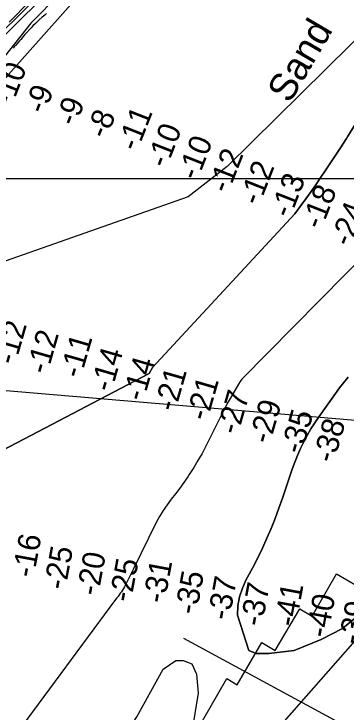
# Model space of a CAD drawing. Extents: x 3271442 to 3309282, y 752266 to 777610.
# Drawn here: x 3288016 to 3289012, y 762104 to 764198 of the extents above; entities that cross this region are included whole.
import ezdxf

# ---------------------------------------------------------------- set-up
doc = ezdxf.new("R2010")
doc.units = 0
for name, color, linetype in [('V-GRID-MAJR', 7, 'Continuous'), ('V-RIVR-EDGE', 7, 'Continuous'), ('V-RIVR-IDEN', 7, 'Continuous'), ('V-RIVR-RANG', 7, 'Continuous'), ('V-RRAP-RVMT', 7, 'Continuous'), ('V-SITE-VEGE', 7, 'Continuous'), ('V-TOPO-DPTH', 7, 'Continuous'), ('V-TOPO-MINR', 7, 'Continuous'), ('V-TOPO-WATR', 7, 'Continuous'), ('V-UTIL-LINE', 7, 'Continuous')]:
    doc.layers.add(name, color=color, linetype=linetype)

msp = doc.modelspace()

# ---------------------------------------------------------------- linework, layer by layer
at = {"layer": 'V-GRID-MAJR'}
msp.add_spline([(3275589.54, 763703.55), (3280833.333, 763703.169), (3286077.126, 763703.55), (3291320.919, 763704.694), (3296564.7120000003, 763706.601), (3301808.505, 763709.27), (3307052.2970000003, 763712.703), (3307052.298, 763712.703)], degree=3, dxfattribs=at)
at = {"layer": 'V-RIVR-EDGE'}
msp.add_lwpolyline([(3288063.4095426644, 764236.6794993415), (3288001.5274757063, 764172.9346756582)], dxfattribs=at)
at = {"layer": 'V-RIVR-RANG'}
msp.add_line((3289422.6719, 761839.2634), (3288525.1781, 762323.9333000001), dxfattribs=at)
at = {"layer": 'V-RRAP-RVMT'}
msp.add_lwpolyline([(3288581.339000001, 762077.719999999), (3288654.822000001, 762203.986999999), (3288685.260000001, 762185.760999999), (3288759.040000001, 762311.9149999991), (3288799.675000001, 762288.7039999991), (3288873.009000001, 762413.260999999), (3288910.816000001, 762391.6819999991), (3288983.352000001, 762518.167999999), (3289076.977000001, 762464.6769999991), (3289150.638000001, 762590.8879999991), (3289182.3570000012, 762571.8289999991), (3289254.390000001, 762698.454999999), (3289295.293000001, 762675.1009999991), (3289368.5190000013, 762802.7179999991), (3289377.962000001, 762796.954999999), (3289450.256000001, 762923.790999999), (3289468.066000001, 762913.130999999), (3289533.118000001, 763025.863999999), (3289582.620731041, 762997.3884135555)], dxfattribs=at)
at = {"layer": 'V-SITE-VEGE'}
msp.add_lwpolyline([(3288113.505, 764199.255), (3288110.923, 764197.062), (3288107.9760000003, 764194.87), (3288100.23, 764188.659), (3288091.375, 764180.2440000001), (3288085.1, 764174.028), (3288079.932, 764168.906), (3288072.551, 764161.957), (3288067.384, 764156.835), (3288065.168, 764154.275), (3288051.879, 764140.002), (3288048.182, 764135.976), (3288043.384, 764130.1190000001), (3288040.429, 764126.826), (3288035.9930000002, 764120.966), (3288032.669, 764117.307), (3288027.502, 764111.818), (3288020.114, 764103.397), (3288016.4220000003, 764099.37), (3288013.096, 764095.348)], dxfattribs=at)
at = {"layer": 'V-TOPO-DPTH'}
for points in [[(3290184.530148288, 766309.2501059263), (3289787.21277023, 765875.3592239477), (3289382.1290904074, 765476.0767404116), (3289095.648006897, 765248.0513320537), (3288831.9176185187, 764970.410679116), (3288487.951788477, 764620.5360573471), (3288044.6706308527, 764190.8501860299), (3287922.3783723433, 764069.1612229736), (3287681.5023705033, 763783.8395979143), (3287413.7052602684, 763403.2787936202), (3287207.1862501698, 763136.9333630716), (3286958.572717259, 762805.8841119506), (3286828.392103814, 762577.4722174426), (3286545.1764903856, 762128.3294005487), (3286299.903839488, 761606.6603935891), (3286161.9762684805, 761328.7086664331), (3286012.4329743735, 760978.3532935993), (3285889.4714349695, 760585.9976628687)], [(3285889.4714349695, 760585.9976628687), (3286012.4329743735, 760978.3532935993), (3286161.9762684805, 761328.7086664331), (3286299.903839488, 761606.6603935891), (3286545.1764903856, 762128.3294005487), (3286828.392103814, 762577.4722174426), (3286958.572717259, 762805.8841119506), (3287207.1862501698, 763136.9333630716), (3287413.7052602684, 763403.2787936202), (3287681.5023705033, 763783.8395979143), (3287922.3783723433, 764069.1612229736), (3288044.6706308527, 764190.8501860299), (3288487.951788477, 764620.5360573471), (3288831.9176185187, 764970.410679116), (3289095.648006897, 765248.0513320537), (3289382.1290904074, 765476.0767404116), (3289787.21277023, 765875.3592239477), (3290184.530148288, 766309.2501059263)], [(3290114.443681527, 766120.7103178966), (3289718.462042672, 765685.3607058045), (3289162.1666665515, 765192.4144403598), (3288544.9121681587, 764616.7716762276), (3288268.018930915, 764319.2063145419), (3287999.3967092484, 764016.0973521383), (3287467.6890380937, 763415.3888853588), (3287029.806038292, 762786.832672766), (3286810.8372242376, 762461.5083362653), (3286622.2387147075, 762133.3473282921), (3286222.5736656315, 761325.1942753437), (3286050.3464737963, 760916.9071271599), (3285958.5390493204, 760643.7382713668)], [(3285958.5390493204, 760643.7382713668), (3286050.3464737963, 760916.9071271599), (3286222.5736656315, 761325.1942753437), (3286622.2387147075, 762133.3473282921), (3286810.8372242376, 762461.5083362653), (3287029.806038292, 762786.832672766), (3287467.6890380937, 763415.3888853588), (3287999.3967092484, 764016.0973521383), (3288268.018930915, 764319.2063145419), (3288544.9121681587, 764616.7716762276), (3289162.1666665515, 765192.4144403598), (3289718.462042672, 765685.3607058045), (3290114.443681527, 766120.7103178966)], [(3286606.268422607, 761301.335463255), (3286993.5756648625, 762052.6210506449), (3287562.97, 762669.84), (3288421.440914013, 763119.702667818), (3288431.2514201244, 763136.9510444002), (3288858.495536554, 763597.8571805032), (3288874.8436403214, 763620.3684371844), (3288891.067842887, 763642.9678753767), (3288907.106193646, 763665.6995858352), (3288923.020643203, 763688.5194778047), (3288932.8581336, 763702.7495477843), (3288953.394158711, 763732.8851647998), (3288973.657991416, 763763.2000986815), (3288993.513535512, 763793.7840078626), (3289013.096887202, 763824.5472339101), (3289017.5368289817, 763831.6262076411), (3289039.106212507, 763866.0819795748), (3289060.6359832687, 763900.5624385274), (3289082.106334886, 763935.0799280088), (3289103.5370737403, 763969.6221045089), (3289247.6865036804, 764202.4101642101)], [(3286606.268422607, 761301.335463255), (3286993.5756648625, 762052.6210506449), (3287562.97, 762669.84), (3288421.440914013, 763119.702667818), (3288431.2514201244, 763136.9510444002), (3288858.495536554, 763597.8571805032), (3288874.8436403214, 763620.3684371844), (3288891.067842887, 763642.9678753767), (3288907.106193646, 763665.6995858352), (3288923.020643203, 763688.5194778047), (3288932.8581336, 763702.7495477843), (3288953.394158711, 763732.8851647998), (3288973.657991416, 763763.2000986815), (3288993.513535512, 763793.7840078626), (3289013.096887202, 763824.5472339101), (3289017.5368289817, 763831.6262076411), (3289039.106212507, 763866.0819795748), (3289060.6359832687, 763900.5624385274), (3289082.106334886, 763935.0799280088), (3289103.5370737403, 763969.6221045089), (3289247.6865036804, 764202.4101642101)], [(3289088.7166096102, 763496.1016345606), (3288699.583559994, 763102.6186384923), (3288694.3210212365, 763094.9757737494), (3288689.3700363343, 763087.1037064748), (3288667.4985113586, 763049.7843731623), (3288661.5232681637, 763039.3561729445), (3288655.685813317, 763028.853147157), (3288650.0550409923, 763018.2378830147), (3288644.5620570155, 763007.5477933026), (3288591.3864515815, 762901.5206294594), (3288579.8910701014, 762879.6085495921), (3288567.8748522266, 762857.9986661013), (3288555.0773797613, 762836.8420771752), (3288541.7590709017, 762815.9876846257), (3288537.6161401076, 762809.7546053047), (3288525.721803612, 762792.4332528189), (3288513.487310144, 762775.363570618), (3288500.742581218, 762758.6713938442), (3288487.6576953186, 762742.2308873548), (3288474.9364337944, 762725.5814666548), (3288463.031664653, 762708.4072153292), (3288452.3516340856, 762690.4457180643), (3288442.488095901, 762671.9593901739), (3288373.4722508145, 762530.9721223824), (3288369.579030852, 762523.1104021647), (3288365.6380322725, 762515.2729820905), (3288361.6253657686, 762507.4720122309), (3288357.5649206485, 762499.6953425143), (3288346.900358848, 762479.4964664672), (3288344.107794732, 762474.473102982), (3288341.1750734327, 762469.5371608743), (3288338.0321163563, 762464.7323508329), (3288334.749002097, 762460.0149621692), (3288331.330747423, 762455.3859536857), (3288327.8730832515, 762450.7869749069), (3288324.3563048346, 762446.2330406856), (3288320.80011692, 762441.7091361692), (3287923.60416648, 761904.9226252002)], [(3289088.7166096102, 763496.1016345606), (3288699.583559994, 763102.6186384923), (3288694.3210212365, 763094.9757737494), (3288689.3700363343, 763087.1037064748), (3288667.4985113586, 763049.7843731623), (3288661.5232681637, 763039.3561729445), (3288655.685813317, 763028.853147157), (3288650.0550409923, 763018.2378830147), (3288644.5620570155, 763007.5477933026), (3288591.3864515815, 762901.5206294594), (3288579.8910701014, 762879.6085495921), (3288567.8748522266, 762857.9986661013), (3288555.0773797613, 762836.8420771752), (3288541.7590709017, 762815.9876846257), (3288537.6161401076, 762809.7546053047), (3288525.721803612, 762792.4332528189), (3288513.487310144, 762775.363570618), (3288500.742581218, 762758.6713938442), (3288487.6576953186, 762742.2308873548), (3288474.9364337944, 762725.5814666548), (3288463.031664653, 762708.4072153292), (3288452.3516340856, 762690.4457180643), (3288442.488095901, 762671.9593901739), (3288373.4722508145, 762530.9721223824), (3288369.579030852, 762523.1104021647), (3288365.6380322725, 762515.2729820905), (3288361.6253657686, 762507.4720122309), (3288357.5649206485, 762499.6953425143), (3288346.900358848, 762479.4964664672), (3288344.107794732, 762474.473102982), (3288341.1750734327, 762469.5371608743), (3288338.0321163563, 762464.7323508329), (3288334.749002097, 762460.0149621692), (3288331.330747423, 762455.3859536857), (3288327.8730832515, 762450.7869749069), (3288324.3563048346, 762446.2330406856), (3288320.80011692, 762441.7091361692), (3287923.60416648, 761904.9226252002)], [(3288503.8115970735, 761602.4623719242), (3288623.4777084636, 761835.7945456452), (3288633.924089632, 761851.983337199), (3288644.263976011, 761868.2415972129), (3289076.318100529, 762359.0835930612), (3289585.9346714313, 762757.5127259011), (3289883.541932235, 763118.2456800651)], [(3289052.3151086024, 762396.736234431), (3289001.9729578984, 762354.7118971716), (3288937.5748128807, 762321.5220587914), (3288856.5022315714, 762288.3734515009), (3288780.2526764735, 762279.0336871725), (3288742.139679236, 762279.1279296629), (3288720.3723559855, 762287.8531855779), (3288685.9850085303, 762394.5127517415), (3288687.749567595, 762422.3503231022), (3288692.300088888, 762449.4930144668), (3288701.029553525, 762475.5933858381), (3288712.5449803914, 762500.9988772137), (3288716.8593966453, 762508.81103231), (3288732.1656074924, 762537.4018258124), (3288746.9666213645, 762566.2436012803), (3288761.009839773, 762595.4618496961), (3288774.5478612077, 762624.9310800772), (3288787.28476525, 762654.7529318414), (3288799.4605163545, 762684.7931745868), (3288810.794538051, 762715.1610038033), (3288821.5674068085, 762745.747224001), (3288850.6092600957, 762832.0214605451), (3288858.1880503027, 762852.9910479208), (3288866.3713595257, 762873.7062530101), (3288875.4614472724, 762894.0398846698), (3288885.156054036, 762914.1191340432), (3288895.7284208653, 762933.7504178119), (3288906.8613451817, 762953.0414859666), (3288918.835105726, 762971.8222307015), (3288931.369423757, 762990.2627598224), (3288980.418029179, 763059.1008599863), (3288992.7784801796, 763075.9523852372), (3289005.440692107, 763092.5673011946), (3289018.5555454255, 763108.8273032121)], [(3289018.5555454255, 763108.8273032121), (3289005.440692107, 763092.5673011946), (3288992.7784801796, 763075.9523852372), (3288980.418029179, 763059.1008599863), (3288931.369423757, 762990.2627598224), (3288918.835105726, 762971.8222307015), (3288906.8613451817, 762953.0414859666), (3288895.7284208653, 762933.7504178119), (3288885.156054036, 762914.1191340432), (3288875.4614472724, 762894.0398846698), (3288866.3713595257, 762873.7062530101), (3288858.1880503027, 762852.9910479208), (3288850.6092600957, 762832.0214605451), (3288821.5674068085, 762745.747224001), (3288810.794538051, 762715.1610038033), (3288799.4605163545, 762684.7931745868), (3288787.28476525, 762654.7529318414), (3288774.5478612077, 762624.9310800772), (3288761.009839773, 762595.4618496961), (3288746.9666213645, 762566.2436012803), (3288732.1656074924, 762537.4018258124), (3288716.8593966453, 762508.81103231), (3288712.5449803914, 762500.9988772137), (3288701.029553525, 762475.5933858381), (3288692.300088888, 762449.4930144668), (3288687.749567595, 762422.3503231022), (3288685.9850085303, 762394.5127517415), (3288720.3723559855, 762287.8531855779)], [(3288720.3723559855, 762287.8531855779), (3288742.139679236, 762279.1279296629), (3288780.2526764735, 762279.0336871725), (3288856.5022315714, 762288.3734515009), (3288937.5748128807, 762321.5220587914), (3289001.9729578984, 762354.7118971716), (3289052.3151086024, 762396.736234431)], [(3288644.263976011, 761868.2415972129), (3289076.318100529, 762359.0835930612)], [(3287924.788452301, 761194.921941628), (3288044.845773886, 761580.5215308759), (3288154.956645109, 761797.0182555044), (3288250.462964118, 761887.3010177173), (3288286.3175922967, 761937.2359742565), (3288384.3591176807, 762089.446466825), (3288463.3205838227, 762232.1758313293), (3288501.4983727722, 762258.2842744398), (3288522.9369337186, 762258.2312630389), (3288549.116058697, 762248.6382220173), (3288563.3318606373, 762217.6360708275), (3288567.954621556, 762160.4547946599), (3288529.2526087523, 761922.3428044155), (3288507.6609037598, 761860.4621953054), (3288419.526005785, 761618.5226630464), (3288503.8115970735, 761602.4623719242)], [(3288549.116058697, 762248.6382220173), (3288563.3318606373, 762217.6360708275), (3288567.954621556, 762160.4547946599), (3288529.2526087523, 761922.3428044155), (3288507.6609037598, 761860.4621953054), (3288251.036748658, 761156.0019930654), (3288215.23513188, 761127.5055974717), (3288165.182372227, 761115.7189791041), (3288112.7711108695, 761113.466500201), (3288048.461318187, 761116.0075967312), (3287998.461569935, 761125.6595393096), (3287955.60211851, 761132.9117490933), (3287934.2106788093, 761152.0212591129), (3287924.788452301, 761194.921941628), (3288044.845773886, 761580.5215308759), (3288154.956645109, 761797.0182555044), (3288250.462964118, 761887.3010177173), (3288286.3175922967, 761937.2359742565), (3288384.3591176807, 762089.446466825), (3288463.3205838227, 762232.1758313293), (3288501.4983727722, 762258.2842744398), (3288522.9369337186, 762258.2312630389), (3288549.116058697, 762248.6382220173)]]:
    msp.add_lwpolyline(points, dxfattribs=at)
at = {"layer": 'V-TOPO-MINR'}
for points in [[(3290158.7756967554, 766323.2975718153), (3289801.9369947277, 765939.2191443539), (3289577.6499217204, 765696.755191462), (3289342.384903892, 765481.9341282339), (3289093.3530695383, 765283.716553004), (3288869.0659965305, 765041.2526001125), (3288642.044680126, 764809.8417059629), (3288448.230339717, 764605.9644448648), (3287900.103551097, 764066.0512154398), (3287672.986635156, 763795.9785155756), (3287365.3816664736, 763363.1719478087), (3287074.4757853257, 762982.7940022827), (3286955.3395839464, 762825.6788490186), (3286916.5207218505, 762762.2586248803), (3286708.55716677, 762420.3376289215), (3286528.33210089, 762128.0563834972), (3286389.530398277, 761835.6727099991), (3286139.713282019, 761319.8760163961), (3286031.3774834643, 761063.3174771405), (3285992.5108216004, 760980.5663501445), (3285886.6839246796, 760621.823352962)], [(3290214.07538047, 766293.6373779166), (3289929.0505845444, 765972.0437221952), (3289602.367368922, 765641.4625835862), (3289131.850990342, 765217.3435722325), (3288509.01874854, 764619.6220047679), (3288066.0564886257, 764170.5806900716), (3287952.4775450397, 764027.2596674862), (3287426.217875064, 763396.1604105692), (3286982.8800455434, 762795.2334305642), (3286686.1779077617, 762304.4068400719), (3286189.394003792, 761308.7068724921), (3286031.0360565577, 760925.2395995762), (3285942.017503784, 760663.1101454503)], [(3285958.5390493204, 760643.7382713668), (3286050.3464737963, 760916.9071271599), (3286222.5736656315, 761325.1942753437), (3286622.2387147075, 762133.3473282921), (3286810.8372242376, 762461.5083362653), (3287029.806038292, 762786.832672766), (3287467.6890380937, 763415.3888853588), (3287999.3967092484, 764016.0973521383), (3288268.018930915, 764319.2063145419), (3288544.9121681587, 764616.7716762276), (3289162.1666665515, 765192.4144403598), (3289718.462042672, 765685.3607058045), (3290114.443681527, 766120.7103178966)], [(3289173.8214334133, 764252.6523497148), (3288654.96, 763740.04), (3288538.5250245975, 763649.5890315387), (3287621.5700000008, 763327.54), (3287063.4120887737, 762745.7784618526), (3287059.2437056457, 762743.3252925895), (3287056.1428824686, 762739.6133722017), (3287053.753765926, 762735.0622843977), (3286685.7045300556, 762164.7204155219), (3286683.1291622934, 762163.2829335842), (3286680.9002365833, 762161.3514151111), (3286678.9022722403, 762159.0905389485), (3286655.023310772, 762125.6251792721), (3286644.137062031, 762108.880694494), (3286634.267990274, 762091.6117797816), (3286625.92468399, 762073.5562201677), (3286618.59855469, 762054.9762306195)], [(3289247.6865036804, 764202.4101642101), (3289103.5370737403, 763969.6221045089), (3289082.106334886, 763935.0799280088), (3289060.6359832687, 763900.5624385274), (3289039.106212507, 763866.0819795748), (3289017.5368289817, 763831.6262076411), (3289013.096887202, 763824.5472339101), (3288993.513535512, 763793.7840078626), (3288973.657991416, 763763.2000986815), (3288953.394158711, 763732.8851647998), (3288932.8581336, 763702.7495477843), (3288923.020643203, 763688.5194778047), (3288907.106193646, 763665.6995858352), (3288891.067842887, 763642.9678753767), (3288874.8436403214, 763620.3684371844), (3288858.495536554, 763597.8571805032), (3288431.2514201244, 763136.9510444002), (3288421.440914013, 763119.702667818), (3287562.97, 762669.84), (3286993.5756648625, 762052.6210506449), (3286606.268422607, 761301.335463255)], [(3289088.7166096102, 763496.1016345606), (3288699.583559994, 763102.6186384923), (3288694.3210212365, 763094.9757737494), (3288689.3700363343, 763087.1037064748), (3288667.4985113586, 763049.7843731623), (3288661.5232681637, 763039.3561729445), (3288655.685813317, 763028.853147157), (3288650.0550409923, 763018.2378830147), (3288644.5620570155, 763007.5477933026), (3288591.3864515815, 762901.5206294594), (3288579.8910701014, 762879.6085495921), (3288567.8748522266, 762857.9986661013), (3288555.0773797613, 762836.8420771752), (3288541.7590709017, 762815.9876846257), (3288537.6161401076, 762809.7546053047), (3288525.721803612, 762792.4332528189), (3288513.487310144, 762775.363570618), (3288500.742581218, 762758.6713938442), (3288487.6576953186, 762742.2308873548), (3288474.9364337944, 762725.5814666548), (3288463.031664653, 762708.4072153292), (3288452.3516340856, 762690.4457180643), (3288442.488095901, 762671.9593901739), (3288373.4722508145, 762530.9721223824), (3288369.579030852, 762523.1104021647), (3288365.6380322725, 762515.2729820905), (3288361.6253657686, 762507.4720122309), (3288357.5649206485, 762499.6953425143), (3288346.900358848, 762479.4964664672), (3288344.107794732, 762474.473102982), (3288341.1750734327, 762469.5371608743), (3288338.0321163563, 762464.7323508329), (3288334.749002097, 762460.0149621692), (3288331.330747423, 762455.3859536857), (3288327.8730832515, 762450.7869749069), (3288324.3563048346, 762446.2330406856), (3288320.80011692, 762441.7091361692), (3287923.60416648, 761904.9226252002)], [(3289018.5555454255, 763108.8273032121), (3289005.440692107, 763092.5673011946), (3288992.7784801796, 763075.9523852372), (3288980.418029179, 763059.1008599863), (3288931.369423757, 762990.2627598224), (3288918.835105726, 762971.8222307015), (3288906.8613451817, 762953.0414859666), (3288895.7284208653, 762933.7504178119), (3288885.156054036, 762914.1191340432), (3288875.4614472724, 762894.0398846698), (3288866.3713595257, 762873.7062530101), (3288858.1880503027, 762852.9910479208), (3288850.6092600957, 762832.0214605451), (3288821.5674068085, 762745.747224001), (3288810.794538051, 762715.1610038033), (3288799.4605163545, 762684.7931745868), (3288787.28476525, 762654.7529318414), (3288774.5478612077, 762624.9310800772), (3288761.009839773, 762595.4618496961), (3288746.9666213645, 762566.2436012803), (3288732.1656074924, 762537.4018258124), (3288716.8593966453, 762508.81103231), (3288712.5449803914, 762500.9988772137), (3288701.029553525, 762475.5933858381), (3288692.300088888, 762449.4930144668), (3288687.749567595, 762422.3503231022), (3288685.9850085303, 762394.5127517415), (3288720.3723559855, 762287.8531855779), (3288742.139679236, 762279.1279296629), (3288780.2526764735, 762279.0336871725), (3288856.5022315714, 762288.3734515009), (3288937.5748128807, 762321.5220587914), (3289001.9729578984, 762354.7118971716), (3289052.3151086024, 762396.736234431)], [(3288644.263976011, 761868.2415972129), (3289076.318100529, 762359.0835930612)]]:
    msp.add_lwpolyline(points, dxfattribs=at)
msp.add_lwpolyline([(3287924.788452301, 761194.921941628), (3288044.845773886, 761580.5215308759), (3288154.956645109, 761797.0182555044), (3288250.462964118, 761887.3010177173), (3288286.3175922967, 761937.2359742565), (3288384.3591176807, 762089.446466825), (3288463.3205838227, 762232.1758313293), (3288501.4983727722, 762258.2842744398), (3288522.9369337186, 762258.2312630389), (3288549.116058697, 762248.6382220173), (3288563.3318606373, 762217.6360708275), (3288567.954621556, 762160.4547946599), (3288529.2526087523, 761922.3428044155), (3288507.6609037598, 761860.4621953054), (3288251.036748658, 761156.0019930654), (3288215.23513188, 761127.5055974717), (3288165.182372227, 761115.7189791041), (3288112.7711108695, 761113.466500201), (3288048.461318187, 761116.0075967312), (3287998.461569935, 761125.6595393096), (3287955.60211851, 761132.9117490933), (3287934.2106788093, 761152.0212591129)], close=True, dxfattribs=at)
at = {"layer": 'V-TOPO-WATR'}
msp.add_lwpolyline([(3290184.530148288, 766309.2501059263), (3289787.21277023, 765875.3592239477), (3289382.1290904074, 765476.0767404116), (3289095.648006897, 765248.0513320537), (3288831.9176185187, 764970.410679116), (3288487.951788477, 764620.5360573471), (3288044.6706308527, 764190.8501860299), (3287922.3783723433, 764069.1612229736), (3287681.5023705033, 763783.8395979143), (3287413.7052602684, 763403.2787936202), (3287207.1862501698, 763136.9333630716), (3286958.572717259, 762805.8841119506), (3286828.392103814, 762577.4722174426), (3286545.1764903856, 762128.3294005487), (3286299.903839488, 761606.6603935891), (3286161.9762684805, 761328.7086664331), (3286012.4329743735, 760978.3532935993), (3285889.4714349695, 760585.9976628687)], dxfattribs=at)
at = {"layer": 'V-UTIL-LINE'}
msp.add_lwpolyline([(3284680.99, 763349.585), (3290442.161, 762859.978), (3294363.62, 762975.033), (3296343.031, 765526.605)], dxfattribs=at)

# ---------------------------------------------------------------- texts
at = {"layer": 'V-RIVR-IDEN'}
msp.add_text('Sand  ', height=82.99983200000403, rotation=59.52808775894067, dxfattribs=at).set_placement((3288842.939625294, 763927.0194166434))
at = {"layer": 'V-RIVR-RANG'}
for s, rotation, p in [('-10', 68.5406111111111, (3288008.0713013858, 763916.3468995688)), ('-9', 68.5406111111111, (3288107.0273968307, 763894.7435007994)), ('-9', 68.5406111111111, (3288200.0003968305, 763857.9195007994)), ('-8', 68.5406111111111, (3288292.683892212, 763820.3590200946)), ('-11', 68.5406111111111, (3288385.367387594, 763782.7995393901)), ('-10', 68.5406111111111, (3288472.9363013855, 763732.2278995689)), ('-10', 68.5406111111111, (3288565.9093013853, 763695.4038995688)), ('-12', 68.5406111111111, (3288658.20779061, 763656.8614445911)), ('-12', 68.5406111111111, (3288751.180790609, 763620.037444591)), ('-13', 68.5406111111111, (3288843.9607875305, 763582.7224574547)), ('-18', 68.5406111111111, (3288937.8988029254, 763548.353393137)), ('-24', 68.5406111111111, (3289024.98520902, 763496.5542854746)), ('-12', 73.92094444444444, (3288019.2088889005, 763141.8952737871)), ('-12', 73.92094444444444, (3288115.2288889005, 763113.9612737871)), ('-11', 73.92094444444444, (3288215.8504975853, 763101.9942912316)), ('-14', 73.92094444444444, (3288308.0705189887, 763060.880340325)), ('-14', 73.92094444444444, (3288404.089518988, 763032.9463403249)), ('-21', 73.92094444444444, (3288499.2318316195, 763001.9698131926)), ('-21', 73.92094444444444, (3288595.2508316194, 762974.0358131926)), ('-27', 73.92094444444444, (3288687.3977957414, 762932.6684016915)), ('-29', 73.92094444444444, (3288783.489853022, 762904.9868622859)), ('-35', 73.92094444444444, (3288878.8513374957, 762874.7717169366)), ('-38', 73.92094444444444, (3288975.163566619, 762847.850559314)), ('-16', 79.50625, (3288074.860486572, 762504.2876025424)), ('-25', 79.50625, (3288169.7805669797, 762467.6748595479)), ('-20', 79.50625, (3288268.206692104, 762449.9969628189)), ('-25', 79.50625, (3288366.3445669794, 762430.7618595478)), ('-31', 79.50625, (3288467.3649443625, 762427.0898217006)), ('-35', 79.50625, (3288562.8124835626, 762393.3301240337)), ('-37', 79.50625, (3288661.3827338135, 762376.4303305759)), ('-37', 79.50625, (3288759.664733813, 762357.973330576)), ('-41', 79.50625, (3288861.1655282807, 762356.8949702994)), ('-40', 79.50625, (3288956.757192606, 762323.9133759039)), ('-39', 79.50625, (3289054.5587755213, 762302.863698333))]:
    msp.add_text(s, height=67, rotation=rotation, dxfattribs=at).set_placement(p)

doc.saveas('drawing.dxf')
